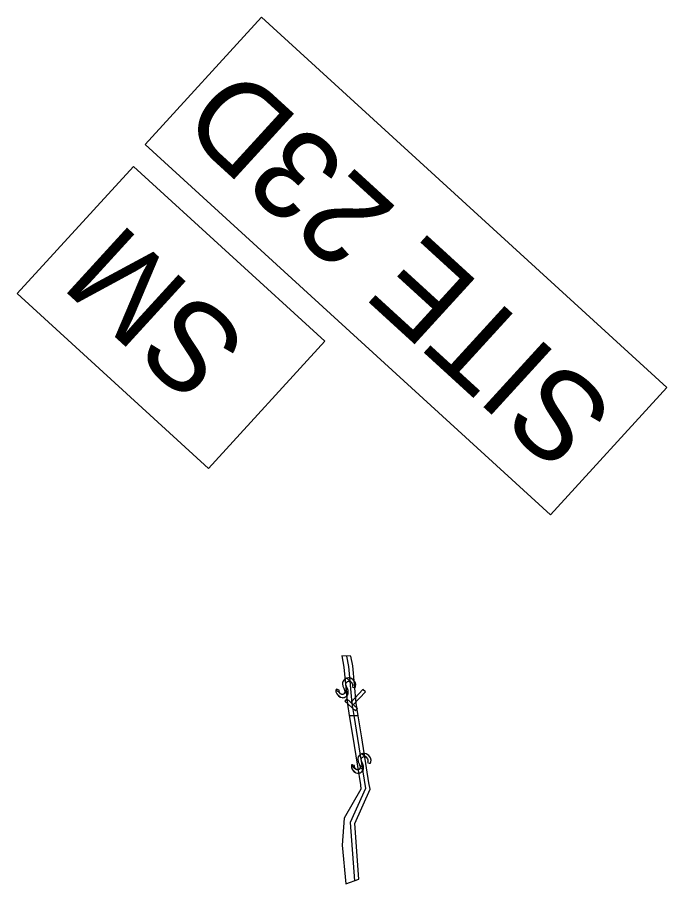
# Model space of a CAD drawing. Extents: x 474218 to 481634, y 484357 to 504997.
# Drawn here: x 476460.6 to 476570.2, y 501019.4 to 501165.6 of the extents above; entities that cross this region are included whole.
import ezdxf

# ---------------------------------------------------------------- set-up
doc = ezdxf.new("R2010")
doc.units = 0
for name, color, linetype in [('Exist Hydro Jurisdictional Stream or Body of Water', 7, 'Continuous'), ('Old_Level_29', 7, 'Continuous'), ('Prop Earthen Structure Impacts In Surface Waters Hatching CELL', 7, 'Continuous'), ('Prop Grid Mask', 7, 'Continuous'), ('Scratch_Level_4', 7, 'Continuous'), ('Temp Earthen Structure Impacts In Surface Waters Hatching CELL', 7, 'Continuous')]:
    doc.layers.add(name, color=color, linetype=linetype)

msp = doc.modelspace()

# ---------------------------------------------------------------- linework, layer by layer
at = {"layer": 'Exist Hydro Jurisdictional Stream or Body of Water'}
msp.add_lwpolyline([(476492.87, 501089.47), (476460.59, 501118.97), (476480.21, 501140.44), (476512.49, 501110.94)], close=True, dxfattribs=at)
at = {"layer": 'Old_Level_29'}
msp.add_lwpolyline([(476550.55, 501081.64), (476482.15, 501144.14), (476501.78, 501165.62), (476570.18, 501103.11)], close=True, dxfattribs=at)
at = {"layer": 'Prop Earthen Structure Impacts In Surface Waters Hatching CELL'}
msp.add_lwpolyline([(476516.05, 501019.36), (476518.2, 501020.1), (476517.53, 501029.53), (476520.11, 501035.34), (476519.94, 501036.41), (476518.72, 501044.01), (476518.13, 501047.72), (476516.61, 501047.77), (476517.16, 501044.42), (476517.98, 501039.18), (476518.48, 501036.03), (476518.59, 501035.33), (476515.76, 501030.41), (476515.39, 501025.85), (476516.05, 501019.36)], dxfattribs=at)
for points in [[(476519.33, 501040.76), (476519.52, 501040.64), (476518.79, 501041.3), (476518.75, 501041.29), (476518.74, 501041.29), (476518.73, 501041.29), (476518.65, 501041.27), (476518.63, 501041.25), (476518.61, 501041.24), (476518.52, 501041.18), (476518.49, 501041.15), (476518.46, 501041.13), (476518.35, 501041.05), (476518.3, 501040.98), (476518.18, 501040.82), (476518.13, 501040.75), (476518.11, 501040.68), (476518.08, 501040.53), (476518.08, 501040.53), (476518.05, 501040.41), (476518.07, 501040.3), (476518.11, 501040.02), (476518.14, 501039.95), (476518.26, 501039.62), (476518.33, 501039.45), (476519.03, 501038.82), (476519.02, 501038.92), (476519.01, 501039.15), (476518.99, 501039.22), (476518.89, 501039.54), (476518.84, 501039.69), (476518.75, 501039.91), (476518.65, 501040.19), (476518.64, 501040.28), (476518.64, 501040.4), (476518.72, 501040.6), (476518.79, 501040.65), (476518.89, 501040.74), (476518.93, 501040.75), (476518.97, 501040.77), (476519.08, 501040.81), (476519.12, 501040.8), (476519.17, 501040.79), (476519.3, 501040.77), (476519.31, 501040.77)], [(476520.19, 501040.63), (476519.89, 501041.01), (476519.47, 501041.29), (476519.46, 501041.29), (476519.07, 501041.36), (476519.02, 501041.37), (476518.79, 501041.3), (476519.52, 501040.64), (476519.68, 501040.44), (476519.69, 501040.43), (476519.69, 501040.41), (476519.75, 501040.27), (476519.77, 501040.21), (476519.76, 501040.19), (476519.76, 501040.05), (476519.75, 501040), (476519.74, 501039.96), (476519.69, 501039.83), (476519.99, 501039.73), (476520.07, 501039.71), (476520.17, 501039.68), (476520.21, 501039.78), (476520.22, 501039.8), (476520.23, 501039.82), (476520.26, 501039.89), (476520.27, 501039.9), (476520.27, 501039.9), (476520.27, 501039.95), (476520.3, 501040.2), (476520.31, 501040.23), (476520.19, 501040.62)], [(476518.85, 501038.41), (476518.93, 501038.51), (476518.44, 501038.96), (476518.41, 501038.81), (476518.29, 501038.66), (476518.28, 501038.65), (476518.24, 501038.63), (476518.11, 501038.57), (476518.05, 501038.57), (476517.96, 501038.57), (476517.92, 501038.58), (476517.89, 501038.59), (476517.81, 501038.63), (476517.71, 501038.69), (476516.99, 501039.34), (476516.97, 501039.28), (476516.97, 501039.04), (476516.96, 501038.99), (476517.08, 501038.68), (476517.73, 501038.09), (476518.02, 501038.02), (476518.1, 501038.01), (476518.31, 501038.05), (476518.39, 501038.06), (476518.42, 501038.07), (476518.45, 501038.08), (476518.46, 501038.08), (476518.48, 501038.1), (476518.53, 501038.13), (476518.57, 501038.15), (476518.68, 501038.22), (476518.72, 501038.25), (476518.73, 501038.26)], [(476517.49, 501039.14), (476517.5, 501039.3), (476517.23, 501039.38), (476517.14, 501039.4), (476517.01, 501039.43), (476517.01, 501039.41), (476517, 501039.4), (476517, 501039.37), (476516.99, 501039.34), (476517.71, 501038.69), (476517.54, 501038.87), (476517.53, 501038.92), (476517.53, 501038.93), (476517.51, 501038.98), (476517.48, 501039.09)], [(476517.69, 501038.11), (476517.73, 501038.09), (476517.08, 501038.68), (476517.09, 501038.66), (476517.37, 501038.32), (476517.37, 501038.32)], [(476519, 501038.74), (476519.03, 501038.82), (476518.33, 501039.45), (476518.41, 501039.28), (476518.46, 501039.03), (476518.44, 501038.96), (476518.93, 501038.51), (476518.95, 501038.57)]]:
    msp.add_lwpolyline(points, close=True, dxfattribs=at)
at = {"layer": 'Prop Grid Mask'}
for points in [[(476570.18, 501103.11), (476501.78, 501165.62), (476482.15, 501144.14), (476550.55, 501081.64)], [(476512.49, 501110.94), (476480.21, 501140.44), (476460.59, 501118.97), (476492.87, 501089.47)]]:
    msp.add_lwpolyline(points, close=True, dxfattribs=at)
at = {"layer": 'Scratch_Level_4'}
for points in [[(476518.13, 501047.72), (476517.79, 501049.86), (476517.21, 501056.12), (476516.9, 501057.77), (476515.37, 501057.81), (476515.72, 501055.91), (476516.3, 501049.67), (476516.61, 501047.77)], [(476516.05, 501019.36), (476518.2, 501020.1), (476517.53, 501029.53), (476520.11, 501035.34), (476519.94, 501036.41), (476518.72, 501044.01), (476518.13, 501047.72), (476516.61, 501047.77), (476517.16, 501044.42), (476517.98, 501039.18), (476518.48, 501036.03), (476518.59, 501035.33), (476515.76, 501030.41), (476515.39, 501025.85)]]:
    msp.add_lwpolyline(points, close=True, dxfattribs=at)
for points in [[(476516.14, 501057.79), (476516.47, 501056.02), (476517.05, 501049.77), (476517.37, 501047.75)], [(476517.37, 501047.75), (476517.98, 501043.89), (476519.33, 501035.44), (476516.77, 501029.67), (476517.47, 501019.85)]]:
    msp.add_lwpolyline(points, dxfattribs=at)
at = {"layer": 'Temp Earthen Structure Impacts In Surface Waters Hatching CELL'}
msp.add_line((476516.61, 501047.77), (476518.13, 501047.72), dxfattribs=at)
msp.add_lwpolyline([(476518.13, 501047.72), (476517.79, 501049.86), (476517.21, 501056.12), (476516.9, 501057.77), (476515.37, 501057.81), (476515.72, 501055.91), (476516.3, 501049.67), (476516.61, 501047.77)], dxfattribs=at)
for points in [[(476516.73, 501053.51), (476516.92, 501053.38), (476516.2, 501054.05), (476516.15, 501054.04), (476516.15, 501054.04), (476516.14, 501054.03), (476516.06, 501054.01), (476516.04, 501054), (476516.02, 501053.98), (476515.93, 501053.92), (476515.9, 501053.9), (476515.87, 501053.87), (476515.76, 501053.79), (476515.71, 501053.73), (476515.59, 501053.57), (476515.54, 501053.5), (476515.52, 501053.42), (476515.48, 501053.27), (476515.48, 501053.27), (476515.46, 501053.15), (476515.48, 501053.04), (476515.52, 501052.77), (476515.55, 501052.69), (476515.67, 501052.36), (476515.74, 501052.19), (476516.44, 501051.56), (476516.43, 501051.66), (476516.42, 501051.89), (476516.4, 501051.96), (476516.3, 501052.29), (476516.24, 501052.43), (476516.16, 501052.65), (476516.05, 501052.93), (476516.05, 501053.03), (476516.05, 501053.15), (476516.13, 501053.34), (476516.19, 501053.39), (476516.3, 501053.48), (476516.33, 501053.5), (476516.38, 501053.51), (476516.49, 501053.55), (476516.53, 501053.55), (476516.58, 501053.54), (476516.71, 501053.52), (476516.72, 501053.51)], [(476517.6, 501053.37), (476517.29, 501053.75), (476516.87, 501054.03), (476516.87, 501054.03), (476516.48, 501054.1), (476516.43, 501054.11), (476516.2, 501054.05), (476516.92, 501053.38), (476517.09, 501053.18), (476517.09, 501053.17), (476517.1, 501053.16), (476517.15, 501053.01), (476517.17, 501052.96), (476517.17, 501052.93), (476517.17, 501052.8), (476517.16, 501052.74), (476517.15, 501052.7), (476517.1, 501052.57), (476517.39, 501052.48), (476517.47, 501052.45), (476517.58, 501052.42), (476517.62, 501052.52), (476517.63, 501052.54), (476517.64, 501052.57), (476517.67, 501052.63), (476517.67, 501052.64), (476517.67, 501052.65), (476517.68, 501052.69), (476517.71, 501052.94), (476517.71, 501052.97), (476517.6, 501053.37)], [(476516.26, 501051.15), (476516.34, 501051.26), (476515.85, 501051.7), (476515.82, 501051.56), (476515.7, 501051.4), (476515.69, 501051.39), (476515.64, 501051.37), (476515.52, 501051.31), (476515.46, 501051.31), (476515.37, 501051.32), (476515.32, 501051.32), (476515.3, 501051.33), (476515.22, 501051.37), (476515.11, 501051.43), (476514.39, 501052.09), (476514.37, 501052.02), (476514.37, 501051.79), (476514.37, 501051.73), (476514.49, 501051.42), (476515.14, 501050.83), (476515.43, 501050.77), (476515.51, 501050.75), (476515.72, 501050.79), (476515.8, 501050.81), (476515.83, 501050.81), (476515.86, 501050.82), (476515.87, 501050.82), (476515.89, 501050.84), (476515.94, 501050.87), (476515.98, 501050.9), (476516.09, 501050.97), (476516.13, 501050.99), (476516.14, 501051)], [(476514.9, 501051.88), (476514.91, 501052.05), (476514.64, 501052.12), (476514.55, 501052.14), (476514.42, 501052.18), (476514.41, 501052.15), (476514.41, 501052.14), (476514.4, 501052.12), (476514.39, 501052.09), (476515.11, 501051.43), (476514.95, 501051.62), (476514.94, 501051.66), (476514.94, 501051.67), (476514.92, 501051.72), (476514.89, 501051.83)], [(476516.41, 501051.48), (476516.44, 501051.56), (476515.74, 501052.19), (476515.81, 501052.02), (476515.86, 501051.77), (476515.85, 501051.7), (476516.34, 501051.26), (476516.36, 501051.32)], [(476517.29, 501049.54), (476519.33, 501051.77), (476518.91, 501052.15), (476516.87, 501049.92)], [(476515.1, 501050.85), (476515.13, 501050.83), (476514.49, 501051.42), (476514.5, 501051.4), (476514.78, 501051.07), (476514.78, 501051.07)], [(476517.65, 501048.55), (476517.98, 501048.91), (476516.19, 501050.55), (476515.86, 501050.19)]]:
    msp.add_lwpolyline(points, close=True, dxfattribs=at)

# ---------------------------------------------------------------- texts
at = {"layer": 'Exist Hydro Jurisdictional Stream or Body of Water'}
msp.add_text('SM', height=15, rotation=137.5803, dxfattribs=at).set_placement((476500.09, 501110.93))
at = {"layer": 'Old_Level_29'}
msp.add_text('SITE 23D', height=15, rotation=137.5803, dxfattribs=at).set_placement((476562, 501099.34))

doc.saveas('drawing.dxf')
